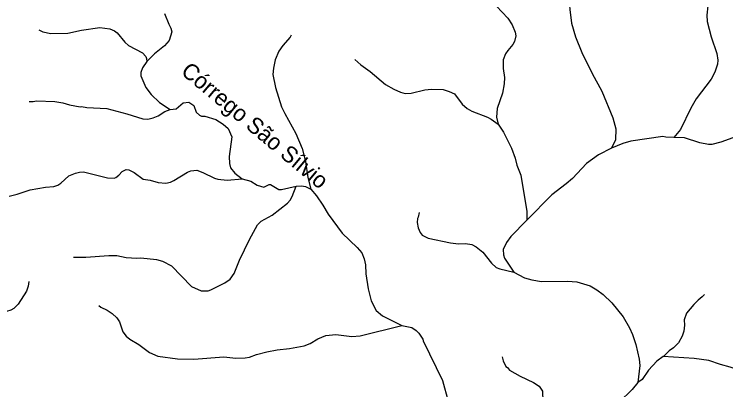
# Model space of a CAD drawing. Extents: x 500 to 555.2, y 9115.7 to 9171.
# Drawn here: x 511.43 to 518.44, y 9130.35 to 9134.05 of the extents above; entities that cross this region are included whole.
import ezdxf
from ezdxf.enums import TextEntityAlignment as Align

# ---------------------------------------------------------------- set-up
doc = ezdxf.new("R2010")
doc.units = 0
doc.header["$LTSCALE"] = 0.064
doc.layers.add('61', color=7, linetype='Continuous')
doc.layers.add('7', color=7, linetype='Continuous', lineweight=25)

msp = doc.modelspace()

# ---------------------------------------------------------------- linework, layer by layer
at = {"layer": '7'}
for points in [[(515.8315, 9134.3813), (516.0516, 9134.2272), (516.1795, 9134.1287), (516.2894, 9134.0106), (516.3323, 9133.9428), (516.3629, 9133.8735), (516.3698, 9133.8353), (516.3575, 9133.7797), (516.3398, 9133.751), (516.2894, 9133.6915), (516.2691, 9133.6583), (516.2453, 9133.6006), (516.2452, 9133.5127), (516.2565, 9133.4241), (516.2549, 9133.3644), (516.2386, 9133.27), (516.1859, 9133.121), (516.1796, 9133.0338), (516.1953, 9132.9642)], [(516.9192, 9134.3171), (516.8964, 9134.1747), (516.9013, 9134.0954), (516.9194, 9133.9615), (516.9568, 9133.8264), (517.0196, 9133.6723), (517.1225, 9133.4634), (517.2161, 9133.2922), (517.3246, 9133.0292), (517.3561, 9132.9184), (517.3532, 9132.8124), (517.3113, 9132.7306)], [(518.261, 9134.132), (518.2529, 9134.0402), (518.2546, 9133.9779), (518.2953, 9133.8277), (518.3512, 9133.6629), (518.3595, 9133.5973), (518.3578, 9133.557), (518.3317, 9133.4766), (518.2955, 9133.4104), (518.1455, 9133.2149), (518.0948, 9133.1236), (517.9908, 9132.9134), (517.9273, 9132.8334)], [(512.9072, 9134.0566), (512.9492, 9133.9498), (512.9697, 9133.9116), (512.979, 9133.8758), (512.9537, 9133.7916), (512.9055, 9133.7384), (512.8092, 9133.6602), (512.7311, 9133.5828)], [(511.6672, 9133.8947), (511.7068, 9133.8757), (511.7874, 9133.8597), (511.9546, 9133.8631), (512.0874, 9133.8907), (512.2679, 9133.9187), (512.3669, 9133.9057), (512.4128, 9133.8862), (512.4396, 9133.8647), (512.5143, 9133.7737), (512.5508, 9133.7404), (512.6902, 9133.6681), (512.7234, 9133.6329), (512.73, 9133.613), (512.7311, 9133.5828)], [(514.1555, 9133.8413), (514.1456, 9133.8225), (514.0742, 9133.7406), (514.0335, 9133.6847), (513.998, 9133.6006), (513.9798, 9133.5174), (513.975, 9133.4551), (514.0014, 9133.3284), (514.0614, 9133.1379), (514.093, 9133.0692), (514.2, 9132.875), (514.2638, 9132.7274), (514.2959, 9132.5995), (514.3193, 9132.44), (514.3502, 9132.3241)], [(512.7311, 9133.5828), (512.6883, 9133.5216), (512.6727, 9133.4759), (512.675, 9133.4406), (512.7243, 9133.3264), (512.7748, 9133.2575), (512.8581, 9133.1801), (512.9621, 9133.1103)], [(514.7823, 9133.6035), (514.8406, 9133.5502), (514.9329, 9133.4857), (515.0845, 9133.3576), (515.1664, 9133.3117), (515.232, 9133.2822), (515.2801, 9133.2678), (515.337, 9133.2711), (515.471, 9133.3052), (515.5373, 9133.3119), (515.6523, 9133.3075), (515.7131, 9133.2891), (515.7639, 9133.2632), (515.8401, 9133.1627), (515.8902, 9133.1189), (515.9342, 9133.0935), (516.0915, 9133.0344), (516.1276, 9133.0146), (516.1953, 9132.9642)], [(511.574, 9133.1884), (511.6132, 9133.1884), (511.6461, 9133.1955), (511.8274, 9133.1888), (511.9055, 9133.1773), (511.9705, 9133.1578), (512.0744, 9133.1367), (512.0892, 9133.1394), (512.1417, 9133.1299), (512.3375, 9133.1216), (512.5348, 9133.0691), (512.6923, 9133.0184), (512.7409, 9133.0135), (512.7959, 9133.0277), (512.8459, 9133.0492), (512.9109, 9133.0915), (512.9621, 9133.1103)], [(512.9621, 9133.1103), (513.0224, 9133.1154), (513.0921, 9133.1752), (513.145, 9133.1837), (513.1973, 9133.1509)], [(513.1973, 9133.1509), (513.2203, 9133.083), (513.25, 9133.0529), (513.2724, 9133.0448), (513.3051, 9133.0445), (513.4134, 9133.0103), (513.4862, 9132.9658), (513.5337, 9132.9216), (513.5713, 9132.8406), (513.5454, 9132.6466), (513.5486, 9132.5771), (513.5574, 9132.5346), (513.6015, 9132.4831), (513.6708, 9132.4285)], [(516.1953, 9132.9642), (516.2469, 9132.8854), (516.3269, 9132.7286), (516.363, 9132.6302), (516.3801, 9132.5625), (516.4175, 9132.4649), (516.4777, 9132.1061), (516.479, 9132.0203)], [(517.9273, 9132.8334), (517.8484, 9132.8362), (517.8174, 9132.8426), (517.5035, 9132.7998), (517.4237, 9132.7763), (517.3113, 9132.7306)], [(518.5092, 9132.8298), (518.3898, 9132.7878), (518.2995, 9132.7643), (518.2686, 9132.7642), (518.1822, 9132.7834), (518.0324, 9132.8296), (517.9273, 9132.8334)], [(517.3113, 9132.7306), (517.1842, 9132.664), (517.0659, 9132.5772), (516.9269, 9132.4306), (516.8656, 9132.3777), (516.7246, 9132.2708), (516.479, 9132.0203)], [(511.3765, 9132.2572), (511.4559, 9132.276), (511.582, 9132.3173), (511.7343, 9132.3441), (511.8171, 9132.3526), (511.8557, 9132.3656), (511.8845, 9132.385), (511.9624, 9132.4556), (512.0281, 9132.4846), (512.0684, 9132.4933), (512.1099, 9132.4947), (512.3439, 9132.4361), (512.4091, 9132.433), (512.4271, 9132.4397), (512.4576, 9132.4623), (512.4885, 9132.4994), (512.5296, 9132.518), (512.5539, 9132.5174), (512.6064, 9132.4888), (512.6962, 9132.4234), (512.7651, 9132.4129), (512.8433, 9132.3901), (512.9212, 9132.3852), (512.9652, 9132.3953), (512.9996, 9132.4101), (513.1325, 9132.4936)], [(513.1325, 9132.4936), (513.1663, 9132.5051), (513.224, 9132.5114), (513.2835, 9132.4898), (513.3994, 9132.4334), (513.4321, 9132.4248), (513.523, 9132.4148), (513.6708, 9132.4285)], [(513.6708, 9132.4285), (513.7579, 9132.4033), (513.8198, 9132.3653), (513.885, 9132.3446), (513.9367, 9132.37), (513.9524, 9132.3704), (514.032, 9132.3232), (514.0597, 9132.3212), (514.2041, 9132.354)], [(512.0114, 9131.6561), (512.1319, 9131.6569), (512.3576, 9131.6716), (512.4364, 9131.6716), (512.5277, 9131.6536), (512.6327, 9131.6454), (512.6731, 9131.6485), (512.8268, 9131.6339), (512.8858, 9131.6158), (512.9761, 9131.5712), (513.1726, 9131.3675), (513.2697, 9131.3224), (513.3367, 9131.3243), (513.3648, 9131.3338), (513.5023, 9131.4034), (513.5538, 9131.4394), (513.5935, 9131.496), (513.6467, 9131.6251), (513.7431, 9131.8311), (513.8246, 9131.9746), (513.8588, 9132.0112), (513.9689, 9132.0706), (514.1177, 9132.1866), (514.1439, 9132.2162), (514.1655, 9132.2529), (514.2041, 9132.354)], [(514.2041, 9132.354), (514.2557, 9132.3583), (514.2964, 9132.3516), (514.3502, 9132.3241)], [(514.3502, 9132.3241), (514.4035, 9132.2598), (514.4662, 9132.1684), (514.5184, 9132.0795), (514.6582, 9131.8909), (514.8071, 9131.7499), (514.8508, 9131.6979), (514.874, 9131.6382), (514.8885, 9131.5805), (514.8904, 9131.4906), (514.9134, 9131.343), (514.9447, 9131.2249), (514.9918, 9131.1292), (515.056, 9131.0779), (515.2472, 9130.9806)], [(515.4182, 9132.0944), (515.4079, 9132.0495), (515.3999, 9132.0368), (515.3973, 9131.9959), (515.4064, 9131.9443), (515.4276, 9131.8992), (515.4473, 9131.8716), (515.5047, 9131.8424), (515.7248, 9131.7966), (515.805, 9131.7865), (515.8744, 9131.7897), (515.9356, 9131.7812), (515.9794, 9131.7569), (516.0449, 9131.7044), (516.1299, 9131.5951), (516.1769, 9131.5549), (516.213, 9131.5402), (516.3481, 9131.5077)], [(516.479, 9132.0203), (516.3211, 9131.8591), (516.2764, 9131.7995), (516.2452, 9131.7308), (516.2481, 9131.6775), (516.2567, 9131.6455), (516.3481, 9131.5077)], [(516.3481, 9131.5077), (516.4558, 9131.453), (516.5255, 9131.4318), (516.6218, 9131.4158), (516.879, 9131.4206), (516.9708, 9131.4123), (517.1008, 9131.3716), (517.167, 9131.3337), (517.2314, 9131.2873), (517.3142, 9131.2063), (517.4274, 9131.0669), (517.4908, 9130.9583), (517.5196, 9130.8941), (517.5522, 9130.7964), (517.5834, 9130.6496), (517.5901, 9130.5884), (517.5727, 9130.4215)], [(511.571, 9131.4155), (511.5638, 9131.3704), (511.547, 9131.3201), (511.4661, 9131.1938), (511.4227, 9131.1483), (511.3928, 9131.133), (511.3067, 9131.1069), (511.2341, 9131.0736), (511.1389, 9131.0524), (511.1045, 9131.0312)], [(518.2288, 9131.2883), (518.2068, 9131.2632), (518.1647, 9131.2324), (518.1224, 9131.1901), (518.0515, 9131.1047), (518.0296, 9131.0373), (518.0313, 9130.9847), (518.025, 9130.9275), (518.0091, 9130.8758), (517.971, 9130.8127), (517.9227, 9130.7626), (517.8813, 9130.7326), (517.8262, 9130.6777), (517.8228, 9130.6753)], [(512.2585, 9131.1779), (512.2786, 9131.1629), (512.3423, 9131.1345), (512.3905, 9131.1008), (512.4364, 9131.0565), (512.4625, 9131.0168), (512.4954, 9130.9203), (512.5291, 9130.8755), (512.5638, 9130.8476), (512.6551, 9130.7948), (512.7574, 9130.7157), (512.8414, 9130.6789), (513.0355, 9130.6547), (513.1955, 9130.6514), (513.4921, 9130.6727), (513.6102, 9130.6613), (513.7009, 9130.6631), (513.7457, 9130.6708), (513.8132, 9130.6973), (513.914, 9130.7238), (514.0183, 9130.7433), (514.1399, 9130.7554), (514.2827, 9130.7824), (514.3413, 9130.8059), (514.4184, 9130.8517), (514.4973, 9130.8827), (514.5953, 9130.8926), (514.7519, 9130.8745), (514.8352, 9130.8807), (515.2472, 9130.9806)], [(515.2472, 9130.9806), (515.3445, 9130.9612), (515.3856, 9130.9335), (515.4135, 9130.9056), (515.4543, 9130.8482), (515.4565, 9130.8327), (515.6452, 9130.44), (515.704, 9130.2374), (515.7268, 9130.1297), (515.7435, 9129.9839), (515.7581, 9129.9117), (515.7596, 9129.845), (515.7492, 9129.774), (515.7249, 9129.7092), (515.7071, 9129.6771), (515.678, 9129.6431), (515.6218, 9129.5967), (515.5872, 9129.5777), (515.4771, 9129.5371), (515.446, 9129.5058), (515.3982, 9129.4273), (515.3402, 9129.3668)], [(516.2338, 9130.6735), (516.2441, 9130.6339), (516.27, 9130.5794), (516.2861, 9130.5676), (516.3069, 9130.5407), (516.4113, 9130.4831), (516.5432, 9130.4204), (516.5986, 9130.3831), (516.6337, 9130.3346), (516.634, 9130.2335), (516.6572, 9130.1671), (516.6887, 9130.1225), (516.7156, 9130.0973), (516.8053, 9130.0601), (516.8241, 9130.0444), (516.8523, 9129.992), (516.8587, 9129.9383), (516.8521, 9129.9008), (516.8391, 9129.8706), (516.8338, 9129.6601)], [(517.8228, 9130.6753), (517.7588, 9130.6295), (517.6783, 9130.5409), (517.6128, 9130.4493), (517.5727, 9130.4215)], [(518.7598, 9130.3677), (518.735, 9130.4067), (518.6564, 9130.4791), (518.5493, 9130.5473), (518.482, 9130.5728), (518.3867, 9130.5974), (518.2698, 9130.636), (518.1282, 9130.6563), (517.8228, 9130.6753)], [(517.5727, 9130.4215), (517.5725, 9130.42), (517.5159, 9130.3525), (517.3872, 9130.227), (517.2162, 9130.0264), (517.1615, 9129.9357), (517.0964, 9129.8592), (516.8338, 9129.6601)]]:
    msp.add_lwpolyline(points, dxfattribs=at)

# ---------------------------------------------------------------- texts
at = {"layer": '61'}
msp.add_text('Córrego São Sílvio', height=0.16, rotation=320.15, dxfattribs=at).set_placement((513.7475, 9132.8927), align=Align.CENTER)

doc.saveas('drawing.dxf')
